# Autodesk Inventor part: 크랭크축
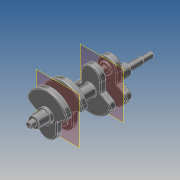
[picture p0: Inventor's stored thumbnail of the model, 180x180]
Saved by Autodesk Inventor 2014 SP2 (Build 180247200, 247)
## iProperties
Created: 2017-03
Part Number: 크랭크축
Material: 강철, 탄소
Document SubType Name: Modeling
Designer: mduedu
Density: 7.87 g/cm^3
Mass: 1840.77 g
Surface Area: 500.249 cm^2
Volume: 233.897 cm^3
Appearance: 반광택
Author: mduedu
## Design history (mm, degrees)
sketch "스케치1" dims "d5" = 57
  geometry: L1 (-19, 21.243)-(-19, 3.243); L2 (-19, 3.243)-(-40.023, -8.895); L3 (19, 21.243)-(19, 3.243); L4 (0, 21.243)-(0, -41); L5 (19, 3.243)-(40.023, -8.895); C1 r 6 at (0, 0); C2 r 13.5 at (0, 0); A1 r 41 centre (0, 0) between (-40.023, -8.895) and (0, -41); A2 r 41 centre (0, 0) between (0, -41) and (40.023, -8.895); A3 r 19 centre (0, 21.243) between (19, 21.243) and (0, 40.243); A4 r 19 centre (0, 21.243) between (0, 40.243) and (-19, 21.243); 3 further points
  constraints: 10 end point, 8 point on circle, 6 centre point, 5 coincident, 3 symmetric about line, 2 point on line, 1 parallel, 1 tangent, 1 vertical, 1 vertical alignment, 5 other
  dimensions: "d0" = 12 diameter of C1; "d1" = 27 diameter of C2; "d2" = 18 distance of L1.start L1.end; "d3" = 120 deg angle of L2 L1; "d4" = 41 radius of A1; "d6" = 19 radius of A4
extrude "돌출1" new body sketch "스케치1" distance "d7" = 12; taper "d8" = 0 deg
extrude "돌출2" join sketch "스케치1" distance "d9" = 5; taper "d10" = 0 deg
extrude "돌출3" join sketch "스케치1" distance "d11" = 75; taper "d12" = 0 deg
sketch "스케치2"
  geometry: C1 r 11 at (0, 21.243); C2 r 6 at (0, 21.243); A1 r 19 centre (0, 21.243) between (19, 21.243) and (-19, 21.243) reference; 1 further point
  constraints: 2 centre point, 2 coincident
  dimensions: "d13" = 22 diameter of C1; "d14" = 12 diameter of C2
extrude "돌출4" join sketch "스케치2" distance "d15" = 3; taper "d16" = 0 deg
extrude "돌출5" join sketch "스케치2" distance "d17" = 16; taper "d18" = 0 deg
fillet "모깎기1" dims "d19" = 3, "d20" = 10
fillet "모깎기2" dims "d21" = 2
sketch "스케치3"
  geometry: C1 r 11 at (0, 0); 1 further point
  constraints: 1 centre point, 1 coincident
  dimensions: "d22" = 22 diameter of C1
extrude "돌출6" join sketch "스케치3" distance "d23" = 21; taper "d24" = 0 deg
sketch "스케치4"
  geometry: C1 r 6 at (0, 0) reference; C2 r 5 at (0, 0); 1 further point
  constraints: 1 centre point
  dimensions: "d25" = 1 radial gap between concentric circles of C1 C2
extrude "돌출7" cut sketch "스케치4" distance "d26" = 20; taper "d27" = 0 deg
node "작업 평면1"
sketch "스케치5"
  geometry: L1 (-5, 0)-(5, 0) reference; L2 (-1.5, 0)-(1.5, 0); L3 (1.5, 0)-(1.5, 8.5); L4 (-1.5, 8.5)-(-1.5, 0); A1 r 1.5 centre (0, 8.5) between (1.5, 8.5) and (-1.5, 8.5); 1 further point
  constraints: 6 end point, 2 point on circle, 2 tangent, 1 centre point, 1 horizontal, 1 parallel, 1 perpendicular, 1 point on line, 1 vertical alignment
  dimensions: "d28" = 3 distance between parallel lines of L3 L4; "d30" = 10 dimension on A1 L1
extrude "돌출8" cut sketch "스케치5" distance "d31" = 1.8; taper "d32" = 0 deg
chamfer "모따기1" distance "d33" = 1; stored, may be unused: second distance "d34" = 2, angle "d35" = 45 deg
chamfer "모따기2" distance "d36" = 1; stored, may be unused: second distance "d37" = 2, angle "d38" = 45 deg
node "작업 평면2"
sketch "스케치6"
  geometry: C1 r 11 at (0, 0) reference; C2 r 11 at (0, 0) reference; 1 further point
extrude "돌출9" join sketch "스케치6" distance "d39" = 42; taper "d40" = 0 deg
sketch "스케치7" dims "d46" = 57
  geometry: L1 (-19, -21.243)-(-19, -3.243); L2 (19, -21.243)-(19, -3.243); L3 (-19, -3.243)-(-40.023, 8.895); L4 (19, -3.243)-(40.023, 8.895); L5 (0, -21.243)-(0, 41); C1 r 13.5 at (0, 0); C2 r 6 at (0, 0); A1 r 19 centre (0, -21.243) between (0, -40.243) and (19, -21.243); A2 r 19 centre (0, -21.243) between (-19, -21.243) and (0, -40.243); A3 r 41 centre (0, 0) between (0, 41) and (-40.023, 8.895); A4 r 41 centre (0, 0) between (40.023, 8.895) and (0, 41); 3 further points
  constraints: 10 end point, 8 point on circle, 6 centre point, 5 coincident, 3 symmetric about line, 2 point on line, 1 parallel, 1 tangent, 1 vertical, 5 other
  dimensions: "d41" = 12 diameter of C2; "d42" = 27 diameter of C1; "d43" = 18 distance of L2.start L2.end; "d44" = 120 deg angle of L4 L2; "d45" = 41 radius of A4; "d47" = 19 radius of A1
extrude "돌출10" join sketch "스케치7" distance "d48" = 12; taper "d49" = 0 deg
sketch "스케치8"
  geometry: C1 r 11 at (0, -21.243); C2 r 6 at (0, -21.243); A1 r 19 centre (0, -21.243) between (-19, -21.243) and (19, -21.243) reference; 1 further point
  constraints: 2 centre point, 2 coincident
  dimensions: "d50" = 22 diameter of C1; "d51" = 12 diameter of C2
extrude "돌출11" join sketch "스케치8" distance "d52" = 3; taper "d53" = 0 deg
extrude "돌출12" join sketch "스케치8" distance "d54" = 16; taper "d55" = 0 deg
fillet "모깎기3" dims "d56" = 3, "d57" = 10
fillet "모깎기4" dims "d58" = 2
chamfer "모따기3" distance "d59" = 1; stored, may be unused: second distance "d60" = 2, angle "d61" = 45 deg
node "작업 평면3"
fillet "모깎기5" dims "d62" = 1
sketch "스케치9"
  geometry: C1 r 13.5 at (0, 0) reference; 1 further point
extrude "돌출13" join sketch "스케치9" distance "d63" = 5; taper "d64" = 0 deg
sketch "스케치10"
  geometry: C1 r 6 at (0, 0) reference; 1 further point
extrude "돌출14" join sketch "스케치10" distance "d65" = 30; taper "d66" = 0 deg
sketch "스케치11"
  geometry: C1 r 11 at (0, 0); 1 further point
  constraints: 1 centre point, 1 coincident
  dimensions: "d67" = 22 diameter of C1
extrude "돌출15" join sketch "스케치11" distance "d68" = 20; taper "d69" = 0 deg
chamfer "모따기4" distance "d70" = 1; stored, may be unused: second distance "d71" = 2, angle "d72" = 45 deg
chamfer "모따기5" distance "d75" = 0.7; stored, may be unused: second distance "d76" = 2, angle "d77" = 30 deg
fillet "모깎기6" dims "d78" = 0.3
node "작업 평면4"
node "작업 평면5"
node "솔리드1"
mirror "대칭1"
mirror "대칭2"
node "투영된 루프1"
